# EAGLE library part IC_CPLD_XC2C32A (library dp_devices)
xc2c32a_vq44-ian edit this description Auto generated by make-symbol-device-package-bsdl.ulp Rev. 29 Source: xc2c32a_vq44-ian.bsd
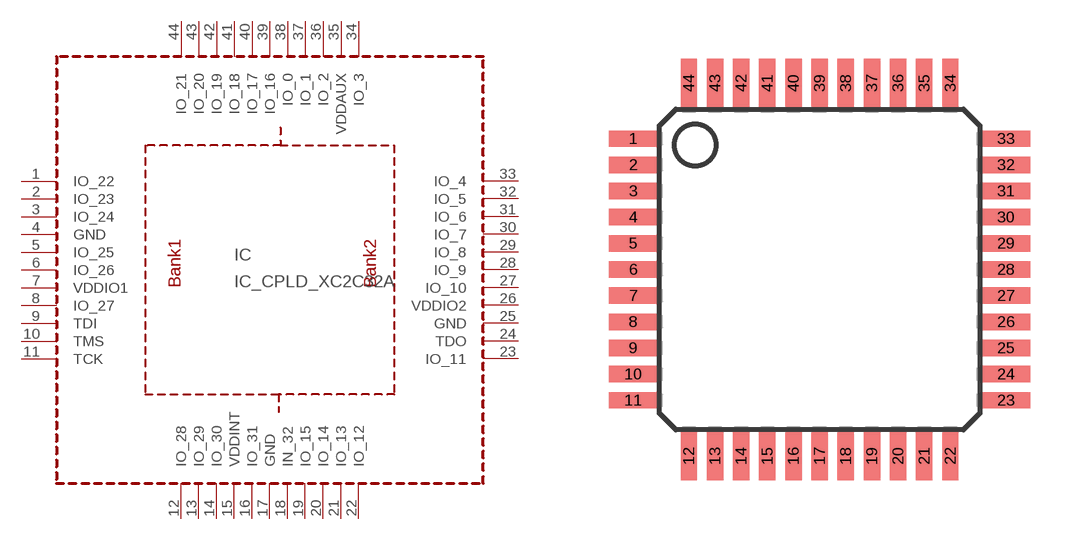
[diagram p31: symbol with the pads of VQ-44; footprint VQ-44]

Designator prefix IC

## IC_CPLD_XC2C32A  [VQ-44]
1  IO_22
2  IO_23
3  IO_24
4  GND  pwr
5  IO_25
6  IO_26
7  VDDIO1  pwr
8  IO_27
9  TDI  in
10  TMS  in
11  TCK  in
12  IO_28
13  IO_29
14  IO_30
15  VDDINT  pwr
16  IO_31
17  GND  pwr
18  IN_32  in
19  IO_15
20  IO_14
21  IO_13
22  IO_12
23  IO_11
24  TDO  out
25  GND  pwr
26  VDDIO2  pwr
27  IO_10
28  IO_9
29  IO_8
30  IO_7
31  IO_6
32  IO_5
33  IO_4
34  IO_3
35  VDDAUX  pwr
36  IO_2
37  IO_1
38  IO_0
39  IO_16
40  IO_17
41  IO_18
42  IO_19
43  IO_20
44  IO_21

## Footprint VQ-44 (pad centres in mm)
smd 1.5 x 0.5: 1 -5.7,4; 2 -5.7,3.2; 3 -5.7,2.4; 4 -5.7,1.6; 5 -5.7,0.8; 6 -5.7,0; 7 -5.7,-0.8; 8 -5.7,-1.6; 9 -5.7,-2.4; 10 -5.7,-3.2; 11 -5.7,-4; 23 5.7,-4; 24 5.7,-3.2; 25 5.7,-2.4; 26 5.7,-1.6; 27 5.7,-0.8; 28 5.7,0; 29 5.7,0.8; 30 5.7,1.6; 31 5.7,2.4; 32 5.7,3.2; 33 5.7,4
smd 0.5 x 1.5: 12 -4,-5.7; 13 -3.2,-5.7; 14 -2.4,-5.7; 15 -1.6,-5.7; 16 -0.8,-5.7; 17 0,-5.7; 18 0.8,-5.7; 19 1.6,-5.7; 20 2.4,-5.7; 21 3.2,-5.7; 22 4,-5.7; 34 4,5.7; 35 3.2,5.7; 36 2.4,5.7; 37 1.6,5.7; 38 0.8,5.7; 39 0,5.7; 40 -0.8,5.7; 41 -1.6,5.7; 42 -2.4,5.7; 43 -3.2,5.7; 44 -4,5.7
